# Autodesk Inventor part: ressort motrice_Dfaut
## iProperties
Created: 2007-07
Part Number: ressort motrice_Dfaut
Document SubType Name: Modeling
Designer: EF
Density: 1 g/cm^3
Author: EF
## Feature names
1. Base1
